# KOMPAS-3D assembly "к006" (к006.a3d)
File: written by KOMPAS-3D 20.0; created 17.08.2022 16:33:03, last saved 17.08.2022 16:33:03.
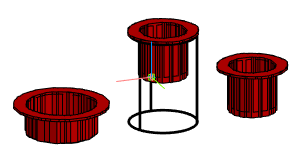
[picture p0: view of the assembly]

Document properties: Автор: artemsv220@gmail.com; Полное имя файла: \\192.168.2.25\новая общая папка\Медиа\Светильники\Кашпо\Кашпо и вазоны\DWG\к006.a3d

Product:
- Part/product: к006
  - Component [detail]: Cylinder149  | qty 6  | source file: \\192.168.2.25\новая общая папка\Медиа\Светильники\Кашпо\Кашпо и вазоны\DWG\Cylinder149_1.m3d
  - Component [detail]: Cylinder156  | qty 3  | source file: \\192.168.2.25\новая общая папка\Медиа\Светильники\Кашпо\Кашпо и вазоны\DWG\Cylinder156.m3d
  - Component [detail]: Torus029  | qty 2  | source file: \\192.168.2.25\новая общая папка\Медиа\Светильники\Кашпо\Кашпо и вазоны\DWG\Torus029.m3d

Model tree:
1. Операция без истории:1
2. Операция без истории:2
3. Операция без истории:3

Referenced files in \\192.168.2.25\новая общая папка\Медиа\Светильники\Кашпо\Кашпо и вазоны\DWG\: Cylinder156.m3d, Torus029.m3d, Cylinder149_1.m3d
